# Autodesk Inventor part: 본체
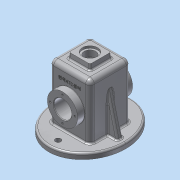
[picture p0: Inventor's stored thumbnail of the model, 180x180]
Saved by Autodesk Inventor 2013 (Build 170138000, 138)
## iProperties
Created: 2017-07
Part Number: 본체
Material: 알루미늄 6061
Document SubType Name: Modeling
Designer: dgall
Density: 2.71 g/cm^3
Mass: 894.433 g
Surface Area: 989.929 cm^2
Volume: 330.049 cm^3
Author: dgall
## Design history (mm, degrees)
sketch "스케치1"
  geometry: L1 (-37, -37)-(37, -37); L2 (37, -37)-(37, 37); L3 (37, 37)-(-37, 37); L4 (-37, 37)-(-37, -37); L5 (-37, -37)-(37, 37); L6 (37, -37)-(-37, 37); 1 further point
  constraints: 12 end point, 2 midpoint, 2 parallel, 1 horizontal, 1 perpendicular
  dimensions: "d12" = 74 distance of L3.end L2.end; "d13" = 74 distance of L2.end L1.end
extrude "돌출1" new body sketch "스케치1" distance "d2" = 110; taper "d3" = 0 deg
feature "쉘1" dims "d4" = 5
sketch "스케치2"
  geometry: L1 (-50, 55)-(-25, 55); L2 (-25, 55)-(-25, 75.5); L3 (-25, 75.5)-(-32, 82.5); L4 (-37, 82.5)-(-50, 82.5); L5 (-50, 82.5)-(-50, 55); L6 (-37, 82.5)-(-32, 82.5); L7 (32, 0)-(-32, 0) reference; L8 (-37, 0)-(-37, 110) reference; L9 (-32, 0)-(-32, 105) reference
  constraints: 12 end point, 3 perpendicular, 2 point on line
  dimensions: "d6" = 55 diameter of L4 L1; "d7" = 13 distance of L4.start L4.end; "d8" = 7 horizontal distance of L2.end L3.end; "d9" = 55 diameter of L3.end L1; "d14" = 55 distance between parallel lines of L7 L1; "d15" = 135 deg angle of L9 L3
revolve "회전1" sketch "스케치2" stored, may be unused: angle "d11" = 90 deg
hole "구멍1" diameter "d18" = 32; stored, may be unused: countersink angle "d22" = 90 deg, drill point angle "d24" = 118 deg; dims "d16" = 10, "d17" = 10, "d19" = 6, "d20" = 4, "d21" = 2, "d23" = 8
fillet "모깎기1" dims "d25" = 8
fillet "모깎기2" dims "d26" = 8
fillet "모깎기3" dims "d27" = 3
fillet "모깎기4" dims "d28" = 3
node "작업 평면1"
sketch "스케치4"
  geometry: L1 (-37, -29)-(-37, 29) reference; L2 (29, -37)-(-29, -37) reference; L3 (37, 29)-(37, -29) reference; L4 (-29, 37)-(29, 37) reference; L5 (0, -75)-(0, 75); L6 (0, 0)-(-65, 0); L7 (0, 0)-(65, 0); A1 r 8 centre (-29, 29) between (-29, 37) and (-37, 29) reference; A2 r 8 centre (-29, -29) between (-37, -29) and (-29, -37) reference; A3 r 8 centre (29, -29) between (29, -37) and (37, -29) reference; A4 r 8 centre (29, 29) between (37, 29) and (29, 37) reference; 2 further points; 1 other entity
  constraints: 6 end point, 2 coincident, 2 perpendicular, 1 midpoint, 1 symmetric about line, 1 vertical, 4 other
  dimensions: "d48" = 150 distance of L5.start L5.end; "d49" = 65 distance of L6.start L6.end
extrude "돌출5" join sketch "스케치4" distance "d50" = 10; taper "d51" = 0 deg
sketch "스케치5"
  geometry: 3 further points; 1 other entity
  constraints: 2 vertical alignment, 1 other
  dimensions: "d52" = 58 distance of point (0, 0) point (0, 58); "d53" = 58 distance of point (0, -58) point (0, 0)
hole "구멍3" sketch "스케치5" at (0, 58), (0, -58) diameter "d54" = 10; stored, may be unused: countersink angle "d58" = 90 deg, drill point angle "d60" = 118 deg; dims "d55" = 6, "d56" = 28, "d57" = 4, "d59" = 8
sketch "스케치6"
  geometry: L1 (-37, 10)-(-37, 102) reference; L2 (65, 10)-(-65, 10) reference; L3 (-55, 10)-(-37, 82.194); L4 (65, 10)-(-65, 10) reference; L5 (65, 0)-(-65, 0) reference; L6 (-37, 82.194)-(-35.802, 87); L7 (-35.802, 87)-(-35.802, 10); L8 (-55, 10)-(-35.802, 10); 1 further point
  constraints: 8 end point, 3 point on line, 2 perpendicular, 1 collinear
  dimensions: "d61" = 10 distance of L3.start L2.end; "d62" = 14 deg angle of L1 L3; "d63" = 77 distance of L6.end L7.end
extrude "돌출6" join sketch "스케치6" stored distance "d64" = 10; taper "d65" = 0 deg
fillet "모깎기6" dims "d67" = 3
fillet "모깎기7" dims "d68" = 3
fillet "모깎기8" dims "d69" = 3
fillet "모깎기9" dims "d70" = 3
fillet "모깎기10" dims "d71" = 3
sketch "스케치7"
  geometry: C1 r 16 at (0, 0) reference; 2 further points
  constraints: 1 vertical alignment
  dimensions: "d78" = 22.5 distance of point (0, 22.5) C1.centre
hole "구멍4" sketch "스케치7" at (0, 22.5) diameter "d79" = 3.459; stored, may be unused: countersink angle "d83" = 90 deg, drill point angle "d85" = 118 deg; dims "d80" = 8, "d81" = 28, "d82" = 4, "d84" = 10
chamfer "모따기1" distance "d89" = 1; stored, may be unused: second distance "d90" = 2, angle "d91" = 45 deg
fillet "모깎기13" dims "d92" = 0.5
sketch "스케치8"
  geometry: L1 (46, 18)-(12, 18) reference; L2 (66, -89)-(66, 0) reference; 2 further points
  constraints: 1 other
  dimensions: "d93" = 37 distance from line of point (29, -12) L2; "d94" = 30 distance from line of point (29, -12) L1
feature "엠보싱1" sketch "스케치8" dims "d2" = 110, "d3" = 0, "d95" = 0.5, "d96" = 0
sketch "스케치9"
  geometry: L1 (-20, -20)-(20, -20); L2 (20, -20)-(20, 20); L3 (20, 20)-(-20, 20); L4 (-20, 20)-(-20, -20); L5 (-20, -20)-(20, 20); L6 (20, -20)-(-20, 20); C1 r 20 at (0, 0) reference
  constraints: 12 end point, 2 midpoint, 2 parallel, 1 horizontal, 1 perpendicular
  dimensions: "d97" = 40 distance of L3.end L2.end; "d98" = 40 distance of L2.end L1.end
extrude "돌출8" join sketch "스케치9" distance "d99" = 10; taper "d100" = -5 deg
sketch "스케치10"
  geometry: 1 further point
hole "구멍5" sketch "스케치10" at (0, 0) diameter "d101" = 21; stored, may be unused: countersink angle "d105" = 90 deg, drill point angle "d107" = 118 deg; dims "d102" = 8, "d103" = 28, "d104" = 4, "d106" = 10
fillet "모깎기14" dims "d108" = 3
fillet "모깎기15" dims "d13" = 74, "d98" = 40, "d109" = 3
fillet "모깎기16" dims "d110" = 0.5
node "솔리드1"
mirror "대칭1"
mirror "대칭2"
pattern_circular "원형 패턴1" dims angle "d87" = 360 deg
mirror "대칭3"
node "투영된 루프1"
